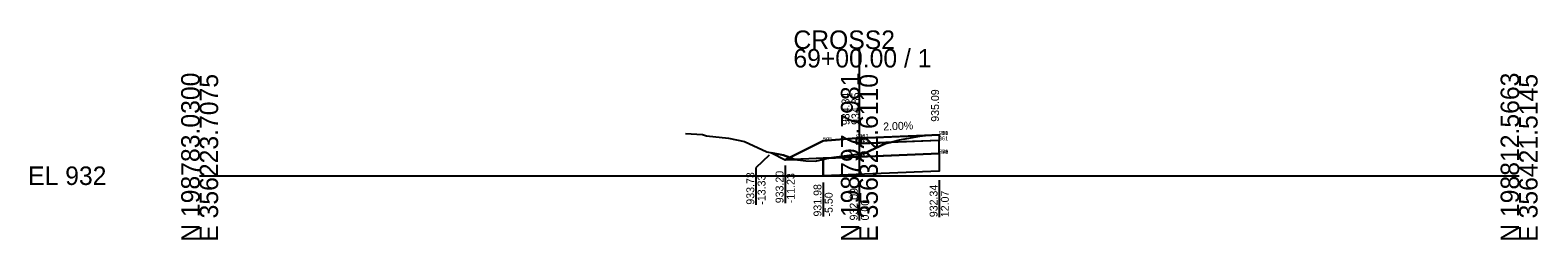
# Model space of a CAD drawing. Extents: x -26 to 203, y -10 to 14021.
# Drawn here: x -25.7 to 202.8, y 9990.3 to 10022 of the extents above; entities that cross this region are included whole.
import ezdxf

# ---------------------------------------------------------------- set-up
doc = ezdxf.new("R2010")
doc.units = 0
for name, color, linetype in [('Default', 7, 'Continuous'), ('P_E_XS_Ground', 7, 'Continuous'), ('P_XS', 7, 'Continuous'), ('P_XS_Bold', 7, 'Continuous'), ('P_XS_EAR_CommonGrnd', 7, 'Continuous'), ('P_XS_Lane', 7, 'Continuous'), ('P_XS_Rock', 7, 'Continuous')]:
    doc.layers.add(name, color=color, linetype=linetype)

msp = doc.modelspace()

# ---------------------------------------------------------------- linework, layer by layer
at = {"layer": 'Default'}
for p, q in [((100, 10000), (100, 10019.18)), ((0, 10000), (100, 10000)), ((100, 10000), (200, 10000))]:
    msp.add_line(p, q, dxfattribs=at)
at = {"layer": 'P_E_XS_Ground'}
for p, q in [((73.66, 10006.39), (76.24, 10006.23)), ((76.24, 10006.23), (76.83, 10006.06)), ((76.83, 10006.06), (80.18, 10005.68)), ((80.18, 10005.68), (82.58, 10005.19)), ((82.58, 10005.19), (85.98, 10003.6)), ((103.98, 10004.86), (106.09, 10005.43)), ((106.09, 10005.43), (109.18, 10005.97)), ((109.18, 10005.97), (110.01, 10006.11)), ((110.01, 10006.11), (111.81, 10006.21)), ((111.81, 10006.21), (112.13, 10006.22)), ((85.98, 10003.6), (88.52, 10003.1)), ((88.52, 10003.1), (90.23, 10002.44)), ((95.19, 10002.65), (100, 10003.24)), ((100, 10003.24), (100.73, 10003.37)), ((100.73, 10003.37), (103.98, 10004.86)), ((90.23, 10002.44), (91.89, 10002.27)), ((91.89, 10002.27), (93.31, 10002.19)), ((93.31, 10002.19), (95.19, 10002.65))]:
    msp.add_line(p, q, dxfattribs=at)
at = {"layer": 'P_XS'}
for p, q in [((99.5, 10005.67), (99.5, 10004.84)), ((112.07, 10005.34), (99.98, 10004.86)), ((112.07, 10006.17), (112.07, 10005.34)), ((112.07, 10003.34), (112.07, 10005.34)), ((99.5, 10004.84), (100, 10004.86)), ((112.07, 10003.34), (99.98, 10002.86)), ((112.07, 10003.34), (112.07, 10000.67)), ((99.5, 10002.84), (88.77, 10002.41)), ((94.5, 10002.64), (94.5, 9999.97)), ((112.07, 10000.67), (94.5, 9999.97)), ((99.5, 10002.84), (100, 10002.86))]:
    msp.add_line(p, q, dxfattribs=at)
at = {"layer": 'P_XS_EAR_CommonGrnd'}
for points in [[(99.5, 10004.84), (99.98, 10004.86), (100, 10004.86), (104.66, 10005.04), (103.98, 10004.86), (100.73, 10003.37), (100, 10003.24), (95.38, 10002.67), (94.5, 10002.64), (90.17, 10002.46), (89.45, 10002.74), (94.5, 10005.27), (99.5, 10005.67)], [(112.07, 10003.34), (112.07, 10005.34), (104.66, 10005.04), (103.98, 10004.86), (100.73, 10003.37), (100, 10003.24), (95.38, 10002.67), (99.5, 10002.84), (99.98, 10002.86), (100, 10002.86)], [(99.5, 10004.84), (99.98, 10004.86), (100, 10004.86), (104.66, 10005.04), (106.09, 10005.43), (109.18, 10005.97), (109.85, 10006.08), (100, 10005.69), (99.5, 10005.67)], [(112.07, 10006.17), (112.07, 10005.34), (104.66, 10005.04), (106.09, 10005.43), (109.18, 10005.97), (109.85, 10006.08)], [(109.85, 10006.08), (110.01, 10006.11), (111.81, 10006.21), (112.07, 10006.22), (112.07, 10006.17)], [(86.67, 10003.46), (88.77, 10002.41), (89.45, 10002.74), (88.52, 10003.1)], [(95.19, 10002.65), (95.38, 10002.67), (99.5, 10002.84), (99.98, 10002.86), (100, 10002.86), (112.07, 10003.34), (112.07, 10000.67), (94.5, 9999.97), (94.5, 10002.48)], [(89.45, 10002.74), (88.77, 10002.41), (90.17, 10002.46)], [(94.5, 10002.64), (90.17, 10002.46), (90.23, 10002.44), (91.89, 10002.27), (93.31, 10002.19), (94.5, 10002.48)], [(95.19, 10002.65), (95.38, 10002.67), (94.5, 10002.64), (94.5, 10002.48)]]:
    msp.add_lwpolyline(points, close=True, dxfattribs=at)
at = {"layer": 'P_XS_Lane'}
for p, q in [((94.5, 10005.27), (88.77, 10002.41)), ((99.5, 10005.67), (94.5, 10005.27)), ((99.5, 10005.67), (100, 10005.69)), ((100, 10005.69), (112.07, 10006.17)), ((112.07, 10006.17), (112.07, 10006.22)), ((86.67, 10003.46), (88.77, 10002.41))]:
    msp.add_line(p, q, dxfattribs=at)
at = {"layer": 'P_XS_Rock'}
for p, q in [((86.31, 10003.12), (84.32, 10001.22)), ((84.32, 10001.22), (84.32, 9995.62)), ((88.75, 10001.54), (88.75, 9995.84)), ((94.5, 9998.96), (94.5, 9993.83)), ((99.99, 9998.91), (99.99, 9993.23)), ((112.1, 9999.32), (112.1, 9993.73))]:
    msp.add_line(p, q, dxfattribs=at)

# ---------------------------------------------------------------- texts
at = {"layer": 'Default'}
for s, p in [('CROSS2', (90, 10019.18)), ('69+00.00 / 1', (90, 10016.38)), ('EL 932', (-26, 9998.6))]:
    msp.add_text(s, height=2.8, dxfattribs=at).set_placement(p)
for s, p in [('N 198783.0300', (0, 9990)), ('E 356223.7075', (2.8, 9990)), ('N 198797.7981', (100, 9990)), ('E 356322.6110', (102.8, 9990)), ('N 198812.5663', (200, 9990)), ('E 356421.5145', (202.8, 9990))]:
    msp.add_text(s, height=2.8, rotation=90, dxfattribs=at).set_placement(p)
at = {"layer": 'P_XS_Bold'}
for s, p in [('505', (94.5, 10005.27)), ('951', (99.5, 10005.67)), ('9', (99.5, 10005.67)), ('900', (99.5, 10005.67)), ('961', (99.5, 10004.84)), ('962', (99.98, 10004.86)), ('952', (100, 10005.69)), ('952', (100, 10005.69)), ('962', (100, 10004.86)), ('951', (112.07, 10006.17)), ('9', (112.07, 10006.17)), ('900', (112.07, 10006.17)), ('910', (112.07, 10006.17)), ('961', (112.07, 10005.34)), ('971', (99.5, 10002.84)), ('998', (99.5, 10002.84)), ('972', (99.98, 10002.86)), ('972', (100, 10002.86)), ('971', (112.07, 10003.34)), ('998', (112.07, 10003.34)), ('540', (112.07, 10003.34))]:
    msp.add_text(s, height=0.6, dxfattribs=at).set_placement(p)
at = {"layer": 'P_XS_Rock'}
for s, rotation, p in [('934.84', 90, (98.5, 10007.65)), ('934.85', 90, (100, 10007.69)), ('934.85', 90, (100, 10007.69)), ('934.85', 90, (100, 10007.69)), ('934.85', 90, (100, 10007.69)), ('935.09', 90, (112.07, 10008.17)), ('2.00%', 2.2906, (103.63, 10006.84)), ('933.20', 90, (88.5, 9995.84)), ('933.73', 90, (84.07, 9995.62)), ('-13.33', 90, (85.77, 9995.62)), ('-11.23', 90, (90.2, 9995.84)), ('931.98', 90, (94.25, 9993.83)), ('932.34', 90, (111.85, 9993.73)), ('-5.50', 90, (95.95, 9993.83)), ('932.09', 90, (99.74, 9993.23)), ('0.00', 90, (101.44, 9993.23)), ('12.07', 90, (113.55, 9993.73))]:
    msp.add_text(s, height=1.2, rotation=rotation, dxfattribs=at).set_placement(p)

doc.saveas('drawing.dxf')
